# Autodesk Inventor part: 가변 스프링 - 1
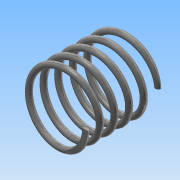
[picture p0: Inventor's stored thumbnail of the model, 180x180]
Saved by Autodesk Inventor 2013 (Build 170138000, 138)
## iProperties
Created: 2016-01
Part Number: 가변 스프링 - 1
Material: 스테인리스강
Document SubType Name: Modeling
Designer: Administrator
Mass: 8.60569 g
Surface Area: 21.6344 cm^2
Volume: 1.06506 cm^3
Density: 8.08 g/cm^3
Author: Administrator
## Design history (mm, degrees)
sketch "스케치1"
  geometry: L1 (0, 0)-(11, 0); L2 (11, 0)-(11, 25.358); L3 (11, 25.358)-(0, 25.358); L4 (0, 25.358)-(0, 0); C1 r 1 at (11, 0)
  constraints: 8 end point, 2 parallel, 1 centre point, 1 coincident, 1 horizontal, 1 perpendicular
  dimensions: "d0" = 2 diameter of C1; "d2" = 22 diameter of L2 L4; "d3" = 25.35829 distance between parallel lines of L1 L3 (derived)
feature "코일1" sketch "스케치1" pitch "d4" = 10; turns "d6" = 5; dims "d5" = 25.35829 (= d3), "d7" = 0, angle "d8" = 90 deg, angle "d9" = 90 deg, "d10" = 0, "d11" = 0
feature "분할1"
node "작업 평면1"
feature "분할2"
node "솔리드1"
other parameters: "d12" = 90 deg
